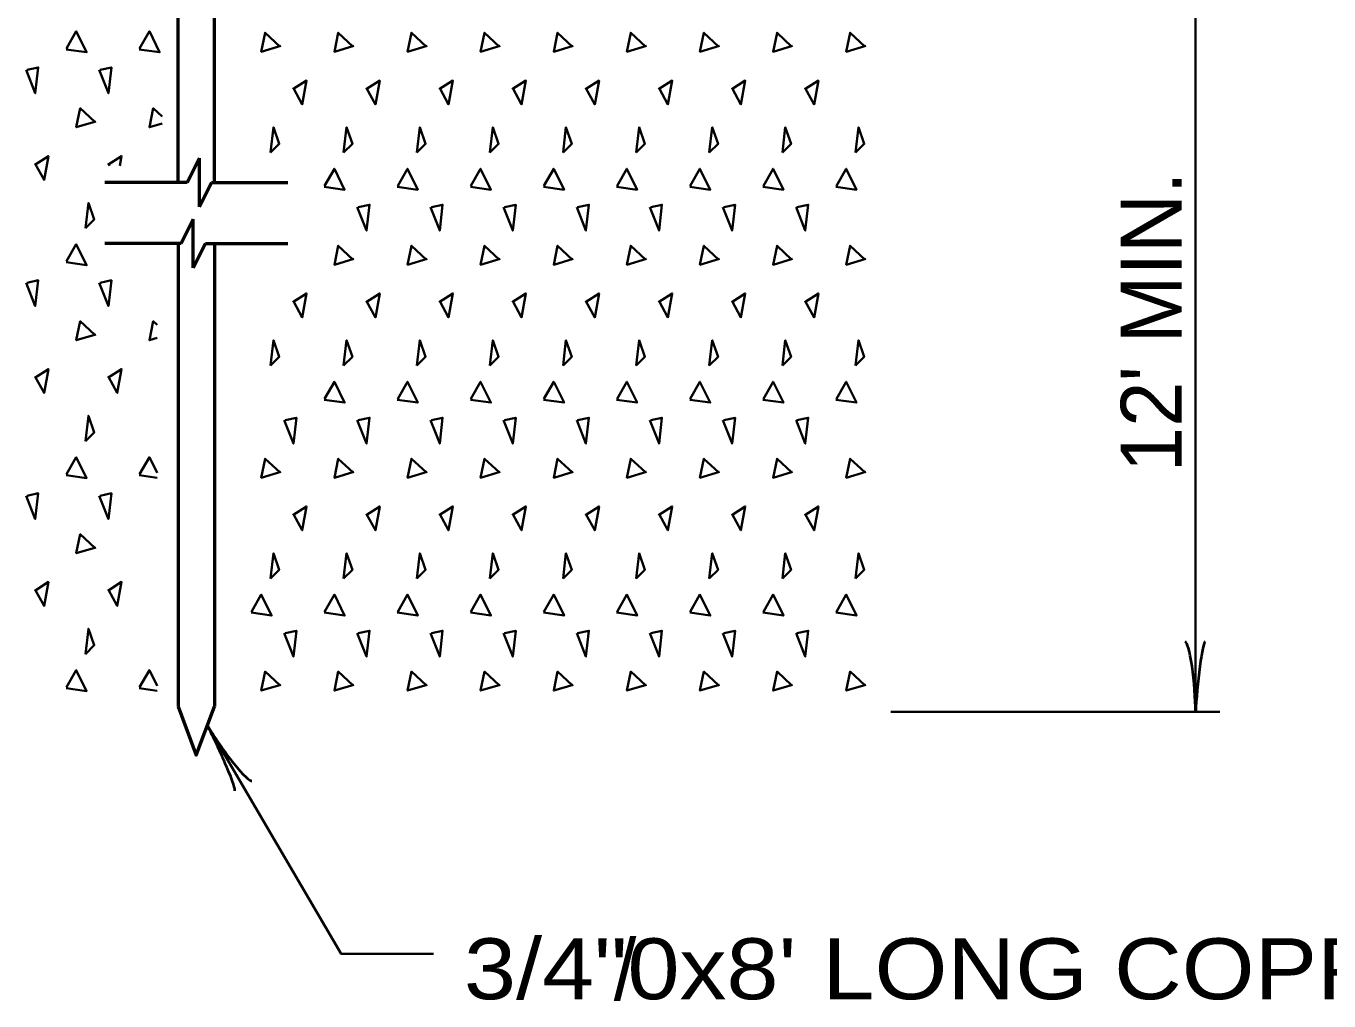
# Model space of a CAD drawing. Extents: x 788 to 1469, y -1 to 439.
# Drawn here: x 915.9 to 969.3, y 78.6 to 118.6 of the extents above; entities that cross this region are included whole.
import ezdxf

# ---------------------------------------------------------------- set-up
doc = ezdxf.new("R2010")
doc.units = 0
doc.layers.add('1', color=7, linetype='Continuous', lineweight=35)

msp = doc.modelspace()

# ---------------------------------------------------------------- linework, layer by layer
at = {"layer": '1', "lineweight": 53}
for p, q in [((923.606, 112.203), (923.606, 146.953)), ((922.481, 112.203), (922.981, 113.203)), ((922.981, 111.203), (922.981, 113.203)), ((922.481, 112.203), (919.106, 112.203)), ((923.481, 112.203), (922.981, 111.203)), ((923.481, 112.203), (926.606, 112.203)), ((922.231, 109.703), (922.731, 110.703)), ((922.731, 108.703), (922.731, 110.703)), ((922.231, 109.703), (919.106, 109.703)), ((922.106, 109.703), (922.106, 90.703)), ((923.231, 109.703), (922.731, 108.703)), ((923.231, 109.703), (926.606, 109.703)), ((923.606, 109.703), (923.606, 90.703))]:
    msp.add_line(p, q, dxfattribs=at)
at = {"layer": '1'}
for p, q in [((919.251, 112.973), (919.297, 112.889)), ((921.244, 100.088), (920.511, 100.193)), ((921.244, 91.348), (920.511, 91.453)), ((951.356, 90.479), (964.856, 90.479))]:
    msp.add_line(p, q, dxfattribs=at)
for points in [[(963.856, 195.872), (963.856, 142.203), (963.856, 131.723), (963.856, 121.729), (963.856, 90.479)], [(917.531, 117.713), (917.931, 118.413), (918.351, 117.553), (917.511, 117.673)], [(920.531, 117.713), (920.931, 118.413), (921.351, 117.553), (920.511, 117.673)], [(926.322, 117.813), (925.521, 117.573), (925.681, 118.353), (926.281, 117.793)], [(929.322, 117.813), (928.521, 117.573), (928.681, 118.353), (929.281, 117.793)], [(932.322, 117.813), (931.521, 117.573), (931.681, 118.353), (932.281, 117.793)], [(935.322, 117.813), (934.521, 117.573), (934.681, 118.353), (935.281, 117.793)], [(938.322, 117.813), (937.521, 117.573), (937.681, 118.353), (938.281, 117.793)], [(941.322, 117.813), (940.521, 117.573), (940.681, 118.353), (941.281, 117.793)], [(944.322, 117.813), (943.521, 117.573), (943.681, 118.353), (944.281, 117.793)], [(947.322, 117.813), (946.521, 117.573), (946.681, 118.353), (947.281, 117.793)], [(950.322, 117.813), (949.521, 117.573), (949.681, 118.353), (950.281, 117.793)], [(915.871, 116.833), (916.251, 115.873), (916.371, 116.933), (915.911, 116.833)], [(918.871, 116.833), (919.251, 115.873), (919.371, 116.933), (918.911, 116.833)], [(926.841, 116.073), (927.202, 115.413), (927.381, 116.393), (926.822, 116.033)], [(929.841, 116.073), (930.202, 115.413), (930.381, 116.393), (929.822, 116.033)], [(932.841, 116.073), (933.202, 115.413), (933.381, 116.393), (932.822, 116.033)], [(935.841, 116.073), (936.202, 115.413), (936.381, 116.393), (935.822, 116.033)], [(938.841, 116.073), (939.202, 115.413), (939.381, 116.393), (938.822, 116.033)], [(941.841, 116.073), (942.202, 115.413), (942.381, 116.393), (941.822, 116.033)], [(944.841, 116.073), (945.202, 115.413), (945.381, 116.393), (944.822, 116.033)], [(947.841, 116.073), (948.202, 115.413), (948.381, 116.393), (947.822, 116.033)], [(918.731, 114.713), (917.931, 114.473), (918.091, 115.253), (918.692, 114.693)], [(921.45, 114.628), (920.931, 114.473), (921.091, 115.253), (921.45, 114.918)], [(916.251, 112.973), (916.611, 112.313), (916.791, 113.293), (916.231, 112.933)], [(919.717, 112.889), (919.791, 113.293), (919.231, 112.933)], [(928.121, 112.073), (928.521, 112.773), (928.942, 111.913), (928.101, 112.033)], [(931.121, 112.073), (931.521, 112.773), (931.942, 111.913), (931.101, 112.033)], [(934.121, 112.073), (934.521, 112.773), (934.942, 111.913), (934.101, 112.033)], [(937.121, 112.073), (937.521, 112.773), (937.942, 111.913), (937.101, 112.033)], [(940.121, 112.073), (940.521, 112.773), (940.942, 111.913), (940.101, 112.033)], [(943.121, 112.073), (943.521, 112.773), (943.942, 111.913), (943.101, 112.033)], [(946.121, 112.073), (946.521, 112.773), (946.942, 111.913), (946.101, 112.033)], [(949.121, 112.073), (949.521, 112.773), (949.942, 111.913), (949.101, 112.033)], [(929.462, 111.193), (929.841, 110.233), (929.962, 111.293), (929.501, 111.193)], [(932.462, 111.193), (932.841, 110.233), (932.962, 111.293), (932.501, 111.193)], [(935.462, 111.193), (935.841, 110.233), (935.962, 111.293), (935.501, 111.193)], [(938.462, 111.193), (938.841, 110.233), (938.962, 111.293), (938.501, 111.193)], [(941.462, 111.193), (941.841, 110.233), (941.962, 111.293), (941.501, 111.193)], [(944.462, 111.193), (944.841, 110.233), (944.962, 111.293), (944.501, 111.193)], [(947.462, 111.193), (947.841, 110.233), (947.962, 111.293), (947.501, 111.193)], [(917.531, 108.973), (917.931, 109.673), (918.351, 108.813), (917.511, 108.933)], [(929.322, 109.073), (928.521, 108.833), (928.681, 109.613), (929.281, 109.053)], [(932.322, 109.073), (931.521, 108.833), (931.681, 109.613), (932.281, 109.053)], [(935.322, 109.073), (934.521, 108.833), (934.681, 109.613), (935.281, 109.053)], [(938.322, 109.073), (937.521, 108.833), (937.681, 109.613), (938.281, 109.053)], [(941.322, 109.073), (940.521, 108.833), (940.681, 109.613), (941.281, 109.053)], [(944.322, 109.073), (943.521, 108.833), (943.681, 109.613), (944.281, 109.053)], [(947.322, 109.073), (946.521, 108.833), (946.681, 109.613), (947.281, 109.053)], [(950.322, 109.073), (949.521, 108.833), (949.681, 109.613), (950.281, 109.053)], [(915.871, 108.093), (916.251, 107.133), (916.371, 108.193), (915.911, 108.093)], [(918.871, 108.093), (919.251, 107.133), (919.371, 108.193), (918.911, 108.093)], [(926.841, 107.333), (927.202, 106.673), (927.381, 107.653), (926.822, 107.293)], [(929.841, 107.333), (930.202, 106.673), (930.381, 107.653), (929.822, 107.293)], [(932.841, 107.333), (933.202, 106.673), (933.381, 107.653), (932.822, 107.293)], [(935.841, 107.333), (936.202, 106.673), (936.381, 107.653), (935.822, 107.293)], [(938.841, 107.333), (939.202, 106.673), (939.381, 107.653), (938.822, 107.293)], [(941.841, 107.333), (942.202, 106.673), (942.381, 107.653), (941.822, 107.293)], [(944.841, 107.333), (945.202, 106.673), (945.381, 107.653), (944.822, 107.293)], [(947.841, 107.333), (948.202, 106.673), (948.381, 107.653), (947.822, 107.293)], [(918.731, 105.973), (917.931, 105.733), (918.091, 106.513), (918.692, 105.953)], [(921.244, 105.826), (920.931, 105.733), (921.091, 106.513), (921.244, 106.37)], [(916.251, 104.233), (916.611, 103.573), (916.791, 104.553), (916.231, 104.193)], [(919.251, 104.233), (919.611, 103.573), (919.791, 104.553), (919.231, 104.193)], [(928.121, 103.333), (928.521, 104.033), (928.942, 103.173), (928.101, 103.293)], [(931.121, 103.333), (931.521, 104.033), (931.942, 103.173), (931.101, 103.293)], [(934.121, 103.333), (934.521, 104.033), (934.942, 103.173), (934.101, 103.293)], [(937.121, 103.333), (937.521, 104.033), (937.942, 103.173), (937.101, 103.293)], [(940.121, 103.333), (940.521, 104.033), (940.942, 103.173), (940.101, 103.293)], [(943.121, 103.333), (943.521, 104.033), (943.942, 103.173), (943.101, 103.293)], [(946.121, 103.333), (946.521, 104.033), (946.942, 103.173), (946.101, 103.293)], [(949.121, 103.333), (949.521, 104.033), (949.942, 103.173), (949.101, 103.293)], [(926.462, 102.453), (926.841, 101.493), (926.962, 102.553), (926.501, 102.453)], [(929.462, 102.453), (929.841, 101.493), (929.962, 102.553), (929.501, 102.453)], [(932.462, 102.453), (932.841, 101.493), (932.962, 102.553), (932.501, 102.453)], [(935.462, 102.453), (935.841, 101.493), (935.962, 102.553), (935.501, 102.453)], [(938.462, 102.453), (938.841, 101.493), (938.962, 102.553), (938.501, 102.453)], [(941.462, 102.453), (941.841, 101.493), (941.962, 102.553), (941.501, 102.453)], [(944.462, 102.453), (944.841, 101.493), (944.962, 102.553), (944.501, 102.453)], [(947.462, 102.453), (947.841, 101.493), (947.962, 102.553), (947.501, 102.453)], [(917.531, 100.233), (917.931, 100.933), (918.351, 100.073), (917.511, 100.193)], [(920.531, 100.233), (920.931, 100.933), (921.244, 100.293)], [(926.322, 100.333), (925.521, 100.093), (925.681, 100.873), (926.281, 100.313)], [(929.322, 100.333), (928.521, 100.093), (928.681, 100.873), (929.281, 100.313)], [(932.322, 100.333), (931.521, 100.093), (931.681, 100.873), (932.281, 100.313)], [(935.322, 100.333), (934.521, 100.093), (934.681, 100.873), (935.281, 100.313)], [(938.322, 100.333), (937.521, 100.093), (937.681, 100.873), (938.281, 100.313)], [(941.322, 100.333), (940.521, 100.093), (940.681, 100.873), (941.281, 100.313)], [(944.322, 100.333), (943.521, 100.093), (943.681, 100.873), (944.281, 100.313)], [(947.322, 100.333), (946.521, 100.093), (946.681, 100.873), (947.281, 100.313)], [(950.322, 100.333), (949.521, 100.093), (949.681, 100.873), (950.281, 100.313)], [(915.871, 99.353), (916.251, 98.393), (916.371, 99.453), (915.911, 99.353)], [(918.871, 99.353), (919.251, 98.393), (919.371, 99.453), (918.911, 99.353)], [(926.841, 98.593), (927.202, 97.933), (927.381, 98.913), (926.822, 98.553)], [(929.841, 98.593), (930.202, 97.933), (930.381, 98.913), (929.822, 98.553)], [(932.841, 98.593), (933.202, 97.933), (933.381, 98.913), (932.822, 98.553)], [(935.841, 98.593), (936.202, 97.933), (936.381, 98.913), (935.822, 98.553)], [(938.841, 98.593), (939.202, 97.933), (939.381, 98.913), (938.822, 98.553)], [(941.841, 98.593), (942.202, 97.933), (942.381, 98.913), (941.822, 98.553)], [(944.841, 98.593), (945.202, 97.933), (945.381, 98.913), (944.822, 98.553)], [(947.841, 98.593), (948.202, 97.933), (948.381, 98.913), (947.822, 98.553)], [(918.731, 97.233), (917.931, 96.993), (918.091, 97.773), (918.692, 97.213)], [(916.251, 95.493), (916.611, 94.833), (916.791, 95.813), (916.231, 95.453)], [(919.251, 95.493), (919.611, 94.833), (919.791, 95.813), (919.231, 95.453)], [(925.121, 94.593), (925.521, 95.293), (925.942, 94.433), (925.101, 94.553)], [(928.121, 94.593), (928.521, 95.293), (928.942, 94.433), (928.101, 94.553)], [(931.121, 94.593), (931.521, 95.293), (931.942, 94.433), (931.101, 94.553)], [(934.121, 94.593), (934.521, 95.293), (934.942, 94.433), (934.101, 94.553)], [(937.121, 94.593), (937.521, 95.293), (937.942, 94.433), (937.101, 94.553)], [(940.121, 94.593), (940.521, 95.293), (940.942, 94.433), (940.101, 94.553)], [(943.121, 94.593), (943.521, 95.293), (943.942, 94.433), (943.101, 94.553)], [(946.121, 94.593), (946.521, 95.293), (946.942, 94.433), (946.101, 94.553)], [(949.121, 94.593), (949.521, 95.293), (949.942, 94.433), (949.101, 94.553)], [(926.462, 93.713), (926.841, 92.753), (926.962, 93.813), (926.501, 93.713)], [(929.462, 93.713), (929.841, 92.753), (929.962, 93.813), (929.501, 93.713)], [(932.462, 93.713), (932.841, 92.753), (932.962, 93.813), (932.501, 93.713)], [(935.462, 93.713), (935.841, 92.753), (935.962, 93.813), (935.501, 93.713)], [(938.462, 93.713), (938.841, 92.753), (938.962, 93.813), (938.501, 93.713)], [(941.462, 93.713), (941.841, 92.753), (941.962, 93.813), (941.501, 93.713)], [(944.462, 93.713), (944.841, 92.753), (944.962, 93.813), (944.501, 93.713)], [(947.462, 93.713), (947.841, 92.753), (947.962, 93.813), (947.501, 93.713)], [(917.531, 91.493), (917.931, 92.193), (918.351, 91.333), (917.511, 91.453)], [(920.531, 91.493), (920.931, 92.193), (921.244, 91.553)], [(926.322, 91.593), (925.521, 91.353), (925.681, 92.133), (926.281, 91.573)], [(929.322, 91.593), (928.521, 91.353), (928.681, 92.133), (929.281, 91.573)], [(932.322, 91.593), (931.521, 91.353), (931.681, 92.133), (932.281, 91.573)], [(935.322, 91.593), (934.521, 91.353), (934.681, 92.133), (935.281, 91.573)], [(938.322, 91.593), (937.521, 91.353), (937.681, 92.133), (938.281, 91.573)], [(941.322, 91.593), (940.521, 91.353), (940.681, 92.133), (941.281, 91.573)], [(944.322, 91.593), (943.521, 91.353), (943.681, 92.133), (944.281, 91.573)], [(947.322, 91.593), (946.521, 91.353), (946.681, 92.133), (947.281, 91.573)], [(950.322, 91.593), (949.521, 91.353), (949.681, 92.133), (950.281, 91.573)], [(923.312, 89.918), (928.793, 80.554), (932.586, 80.554)]]:
    msp.add_lwpolyline(points, dxfattribs=at)
at = {"layer": '1', "lineweight": 53}
for points in [[(922.106, 112.203), (922.106, 146.953), (923.606, 146.953)], [(922.106, 90.703), (922.856, 88.703), (923.606, 90.703)]]:
    msp.add_lwpolyline(points, dxfattribs=at)
at = {"layer": '1'}
for points in [[(925.901, 113.433), (926.021, 114.473), (926.261, 113.793)], [(928.901, 113.433), (929.021, 114.473), (929.261, 113.793)], [(931.901, 113.433), (932.021, 114.473), (932.261, 113.793)], [(934.901, 113.433), (935.021, 114.473), (935.261, 113.793)], [(937.901, 113.433), (938.021, 114.473), (938.261, 113.793)], [(940.901, 113.433), (941.021, 114.473), (941.261, 113.793)], [(943.901, 113.433), (944.021, 114.473), (944.261, 113.793)], [(946.901, 113.433), (947.021, 114.473), (947.261, 113.793)], [(949.901, 113.433), (950.021, 114.473), (950.261, 113.793)], [(918.312, 110.333), (918.431, 111.373), (918.671, 110.693)], [(925.901, 104.693), (926.021, 105.733), (926.261, 105.053)], [(928.901, 104.693), (929.021, 105.733), (929.261, 105.053)], [(931.901, 104.693), (932.021, 105.733), (932.261, 105.053)], [(934.901, 104.693), (935.021, 105.733), (935.261, 105.053)], [(937.901, 104.693), (938.021, 105.733), (938.261, 105.053)], [(940.901, 104.693), (941.021, 105.733), (941.261, 105.053)], [(943.901, 104.693), (944.021, 105.733), (944.261, 105.053)], [(946.901, 104.693), (947.021, 105.733), (947.261, 105.053)], [(949.901, 104.693), (950.021, 105.733), (950.261, 105.053)], [(918.312, 101.593), (918.431, 102.633), (918.671, 101.953)], [(925.901, 95.953), (926.021, 96.993), (926.261, 96.313)], [(928.901, 95.953), (929.021, 96.993), (929.261, 96.313)], [(931.901, 95.953), (932.021, 96.993), (932.261, 96.313)], [(934.901, 95.953), (935.021, 96.993), (935.261, 96.313)], [(937.901, 95.953), (938.021, 96.993), (938.261, 96.313)], [(940.901, 95.953), (941.021, 96.993), (941.261, 96.313)], [(943.901, 95.953), (944.021, 96.993), (944.261, 96.313)], [(946.901, 95.953), (947.021, 96.993), (947.261, 96.313)], [(949.901, 95.953), (950.021, 96.993), (950.261, 96.313)], [(918.312, 92.853), (918.431, 93.893), (918.671, 93.213)]]:
    msp.add_lwpolyline(points, close=True, dxfattribs=at)
at = {"layer": '1', "lineweight": 40}
for centre, major_axis, ratio, start_param, end_param in [((963.58, 91.571), (0.156, -1.786), 0.122415, 0.896353, 3.141593), ((964.068, 91.6), (-0.176, -1.756), 0.07063, 3.140715, 5.41811), ((923.695, 88.844), (0.736, -1.605), 0.07063, 6.282307, 8.559703), ((924.102, 89.116), (-1.037, 1.462), 0.122415, 0.896353, 3.141593)]:
    msp.add_ellipse(centre, major_axis=major_axis, ratio=ratio, start_param=start_param, end_param=end_param, dxfattribs=at)

# ---------------------------------------------------------------- texts
at = {"layer": '1'}
msp.add_text("12' MIN.", height=2.5, rotation=90, dxfattribs=at).set_placement((963.285, 100.319))
at = {"layer": '1', "width": 1.15}
msp.add_text('3/4"0x8\' LONG COPPER CLAD GROUND', height=2.5, dxfattribs=at).set_placement((933.836, 78.686))
at = {"layer": '1'}
msp.add_text('/', height=2.5, dxfattribs=at).set_placement((939.982, 78.652))

doc.saveas('drawing.dxf')
